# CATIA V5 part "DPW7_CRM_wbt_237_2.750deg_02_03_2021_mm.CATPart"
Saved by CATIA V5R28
Part number: DPW7_CRM_wbt_237_2.500deg_02_03_2021
Bounding box of the stored display mesh (mm): x 2349.5 to 66711.891, y 0 to 29504.84, z 2310.119 to 8715.756
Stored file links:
  Z:\Scratch\04_CAD_Allgemein\Flight2Jig\Output\DPW-7\CATPart\DPW7_CRM_wbt_237_2.750deg_02_03_2021.CATPart
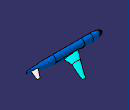
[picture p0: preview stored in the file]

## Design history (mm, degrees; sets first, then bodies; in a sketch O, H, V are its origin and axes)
Set1
  DatumSurface1 "Clean_Wing"
  DatumSurface2 "Fuselage"
  DatumSurface3 "HTP"
  DatumSurface4 "Symmetry"
  DatumSurface5 "Farfield"
Body1 (main body)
